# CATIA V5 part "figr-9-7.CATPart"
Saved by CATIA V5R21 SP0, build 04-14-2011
Part number: Part2
Bounding box of the stored display mesh (mm): x -96.278 to 96.278, y -96.278 to 96.278, z -26.878 to 0
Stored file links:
  D:\CATIA V5R21 E-RESOURCES\CATIA-V5R21\catia-v5r21-prt\c09-catia-v5r20-prt\c09-catia-v5r21-figr-9-7.CATPart
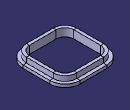
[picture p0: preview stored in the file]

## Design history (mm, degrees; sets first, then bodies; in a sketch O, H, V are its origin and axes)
Body1 (main body)
  Sketch1 on xy-plane, origin (0, 0, 0), H (1, 0, 0), V (0, 1, 0)
    point P1 (-75, 75)
    line L1 (-45, 75) -> (45, 75)
    line L2 (75, 45) -> (75, -45)
    line L3 (45, -75) -> (-45, -75)
    line L4 (-75, -45) -> (-75, 45)
    point P2 (75, 75)
    point P3 (75, -75)
    point P4 (-75, -75)
    axis line L5 (75, -75) -> (-75, 75)
    arc A1 centre (45, -45) radius 30 from (75, -45) to (45, -75) cw
    arc A2 centre (45, 45) radius 30 from (45, 75) to (75, 45) cw
    arc A3 centre (-45, 45) radius 30 from (-45, 75) to (-75, 45) ccw
    arc A4 centre (-45, -45) radius 30 from (-45, -75) to (-75, -45) cw
    distance P2 P3 = 150
    distance P3 P4 = 150
    radius A1 = 30
    radius A2 = 30
    radius A3 = 30
    radius A4 = 30
    horizontal: L1 H, L3 H
    vertical: L2 V, L4 V
    midpoint: O L5
    coincidence: L2 P3, L3 P3, L1 P2, L2 P2, L1 P1, L4 P1, L3 P4, L4 P4
    tangency: A1 L2, A1 L3, A2 L1, A2 L2, A3 L1, A3 L4, A4 L3, A4 L4
  Sketch2 on yz-plane, origin (0, 0, 0), H (0, 1, 0), V (0, 0, 1)
    point P1 (85, 0)
    line L1 (85, 0) -> (85, -16.8782)
    line L2 (85, -16.8782) -> (96.2781, -16.8782)
    line L3 (96.2781, -16.8782) -> (96.2781, -26.8782)
    line L4 (96.2781, -26.8782) -> (75, -26.8782)
    line L5 (75, -26.8782) -> (75, 0)
    point P6 (75, 0)
    line L6 (75, 0) -> (85, 0)
    reference projected point E1 (75, 0) from edge of Sketch1
    length L3 = 10
    length L6 = 10
    coincidence: P1 H, P6 H, P6 E1
    vertical: L1 V, L3 V, L5 V
    horizontal: L2 H, L4 H, L6 H
  Rib1: profile Sketch2, centre curve Sketch1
